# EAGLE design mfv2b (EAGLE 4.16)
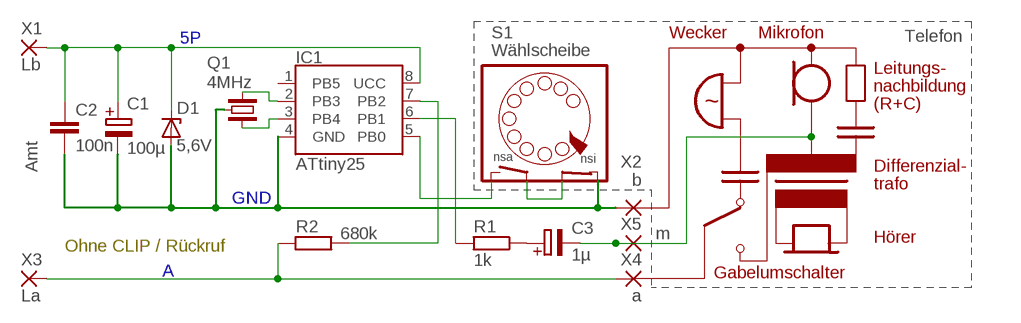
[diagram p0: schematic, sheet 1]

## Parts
C1  100µ  E01-8  [E01-8]
C2  100n  C01  [C1]
C3  1µ  E02-5  [E02-5]
D1  5,6V  DZ-E  [E-LINE-2]
IC1  ATtiny25  ATTINY13P  [DIL08]
Q1  4MHz  RESO  [1×3]
R1  1k  R02  [R02]
R2  680k  R04  [R04]
S1  Wählscheibe  NSK  [1×4]
X1  Lb  WIREPAD1,6/0,8  [1,6/0,8]
X2  b  WIREPAD1,6/0,8  [1,6/0,8]
X3  La  WIREPAD1,6/0,8  [1,6/0,8]
X4  a  WIREPAD1,6/0,8  [1,6/0,8]
X5  m  WIREPAD1,6/0,8  [1,6/0,8]

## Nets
5P: C1.+ C2.1 D1.1(K) IC1.8(UCC) X1.1(P)
A: R2.1 X3.1(P) X4.1(P)
GND: C1.- C2.2 D1.2(A) IC1.4(GND) Q1.2 S1.4 X2.1(P)
N$1: IC1.7(PB2) R2.2
N$2: C3.- X5.1(P)
N$3: IC1.5(PB0) S1.1
N$4: IC1.3(PB4) Q1.3
N$5: IC1.2(PB3) Q1.1
N$6: S1.2 S1.3
N$7: C3.+ R1.1
OUT: IC1.6(PB1) R1.2
Unconnected: IC1.1(PB5)

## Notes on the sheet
- Telefon
- Wecker | Mikrofon
- Leitungs-
- nachbildung
- ~ | (R+C)
- Amt | Differenzial-
- trafo
- Hörer
- Ohne CLIP / Rückruf
- Gabelumschalter

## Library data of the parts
C1 C3 = fu:E: Elektrolytkondensator, gepolt
C2 = fu:C: Kondensator
D1 = fu:DZ: Z-Diode
IC1 = statron:ATTINY13*: AVR-8-bit-Mikrocontroller 64 Byte RAM 64 Byte EEPROM 1 KByte Flash max. 20 MHz 1 8-bit-Timer 10-bit-A/D-Wandler, 4 Eingänge Analogvergleicher Anschlüsse speziell für Rundumleuchte!
Q1 = fu:RESO: Keramik-Resonator Billiger als Quarze, schnellere Hochlaufzeit, ersparen Ballastkondensatoren. Weniger Präzision, Frequenzbereich 4?10,7 MHz.
R1 R2 = fu:R: Widerstand
S1 = fu:NSK: Wählscheibe Nummernschaltkontakt Anschluss vierpolig
X1-X5 = wirepad:WIREPAD: Wire PAD connect wire on PCB

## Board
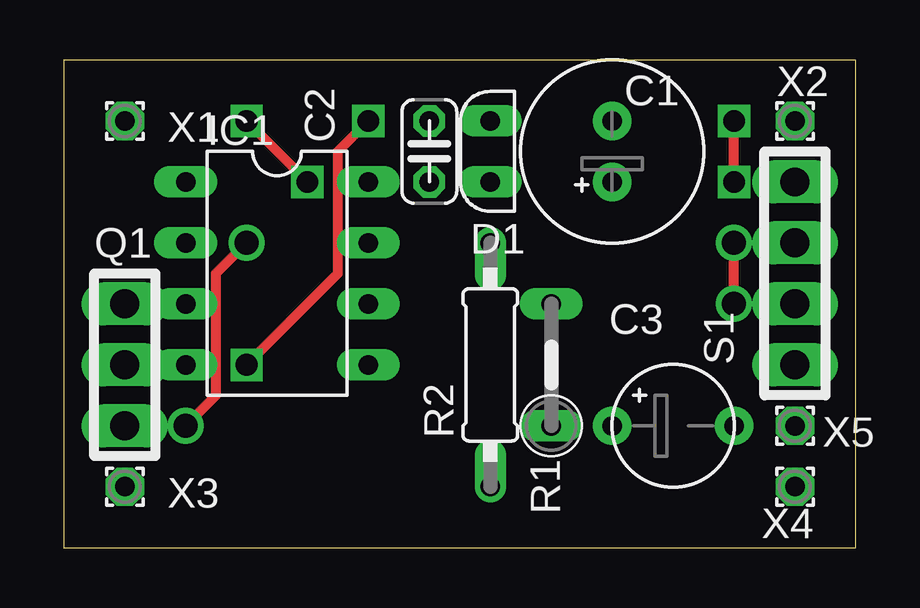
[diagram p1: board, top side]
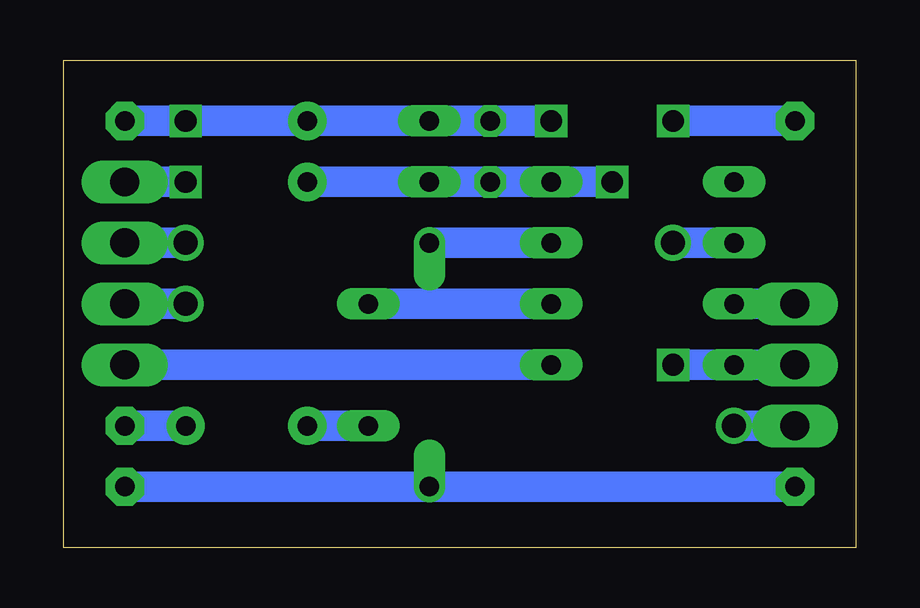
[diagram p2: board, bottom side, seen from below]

Size 33.02 x 20.32 mm. Coordinates in mm from the lower left corner, seen from the top.
Outline: 0,0 33.02,0 33.02,20.32 0,20.32 0,0
Copper layers (1+16): Top 0.035mm / dielectric 1.5mm / Bottom 0.035mm
Design rules "default": minimum track width 10mil, minimum drill 24mil, track to track 8mil, track to pad 8mil, pad to pad 8mil, via to via 8mil, smd to smd 8mil, copper to edge 20mil, drill to drill 8mil, minimum pad ring 10mil, minimum via ring 8mil, stop-mask expansion 4mil, vias tented up to drill 0mil, thermal gap 10mil
bRestrict: area 24.1,14 to 26.7,16.5; area 24.1,11.4 to 26.7,14; area 24.1,8.9 to 26.7,11.4; area 8.9,16.5 to 11.4,19.1; area 6.3,14 to 8.9,16.5; area 8.9,11.4 to 11.4,14; area 6.3,8.9 to 8.9,11.4; area 8.9,6.3 to 11.4,8.9; area 6.3,3.8 to 8.9,6.3; area 24.1,3.8 to 26.7,6.3; area 16.5,3.8 to 19.1,6.3

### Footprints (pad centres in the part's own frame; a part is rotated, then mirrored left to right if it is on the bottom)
E01-8 = drill 0.813 pad 1.6 round: + -1.27,0; - 1.27,0
C1 = drill 0.813 octagon: 1 -1.27,0; 2 1.27,0
E02-5 = drill 0.813 pad 1.6 round: + -2.54,0; - 2.54,0
E-LINE-2 = drill 0.813 long: 1 -1.27,0; 2 1.27,0
DIL08 = drill 0.813 long: 1 -3.81,-3.81; 2 -1.27,-3.81; 3 1.27,-3.81; 4 3.81,-3.81; 5 3.81,3.81; 6 1.27,3.81; 7 -1.27,3.81; 8 -3.81,3.81
1×3 = drill 1.2 long: 1 -2.54,0; 2 0,0; 3 2.54,0
R02 = drill 0.813 long: 1 -2.54,0; 2 2.54,0
R04 = drill 0.813 offset: 1 -5.08,0; 2 5.08,0
1×4 = drill 1.2 long: 1 -3.81,0; 2 -1.27,0; 3 1.27,0; 4 3.81,0
1,6/0,8 = drill 0.813 pad 1.6 octagon: 1 0,0

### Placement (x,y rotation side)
C1  22.86,16.51 90 top
C2  15.24,16.51 90 top
C3  25.4,5.08 0 top
D1  17.78,16.51 90 top
IC1  8.89,11.43 270 top
Q1  2.54,7.62 90 top
R1  20.32,7.62 90 top
R2  17.78,7.62 90 top
S1  30.48,11.43 90 top
X1  2.54,17.78 0 top
X2  30.48,17.78 0 top
X3  2.54,2.54 0 top
X4  30.48,2.54 0 top
X5  30.48,5.08 0 top

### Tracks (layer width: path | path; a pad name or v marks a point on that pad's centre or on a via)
5P  (via drill 0.9)
  Top 0.406: v7.62,17.78 v10.16,15.24
  Bottom 1.27: X1.1 v7.62,17.78 | v10.16,15.24 IC1.8 C2.1 D1.1 C1.+
A
  Bottom 1.27: X3.1 R2.1 X4.1
GND  (via drill 0.9)
  Top 0.406: v7.62,7.62 11.43,11.43 11.43,16.51 v12.7,17.78 | v27.94,15.24 v27.94,17.78
  Bottom 1.27: Q1.2 IC1.4 v7.62,7.62 | v27.94,15.24 S1.4 | X2.1 v27.94,17.78 C1.- D1.2 C2.2 v12.7,17.78
N$1
  Bottom 1.27: IC1.7 R2.2
N$2
  Bottom 1.27: C3.- X5.1
N$3
  Bottom 1.27: IC1.5 S1.1
N$4
  Bottom 1.27: Q1.3 IC1.3
N$5  (via drill 1)
  Top 0.406: v5.08,5.08 6.35,6.35 6.35,11.43 v7.62,12.7
  Bottom 1.27: v7.62,12.7 IC1.2 | v5.08,5.08 Q1.1
N$6  (via drill 1)
  Top 0.406: v27.94,10.16 v27.94,12.7
  Bottom 1.27: v27.94,12.7 S1.3 | v27.94,10.16 S1.2
N$7
  Bottom 1.27: R1.1 C3.+
OUT
  Bottom 1.27: IC1.6 R1.2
